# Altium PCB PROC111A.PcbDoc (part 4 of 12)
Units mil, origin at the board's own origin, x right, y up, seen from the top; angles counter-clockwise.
Board outline 7700 x 2300 mil, 6 copper layers (Top Layer, GND 1, SIG 1, SIG 2, GND 2, Bottom Layer), stack 61.062 mil thick; 841 components, 632 nets, 2914 pads, 1627 vias.
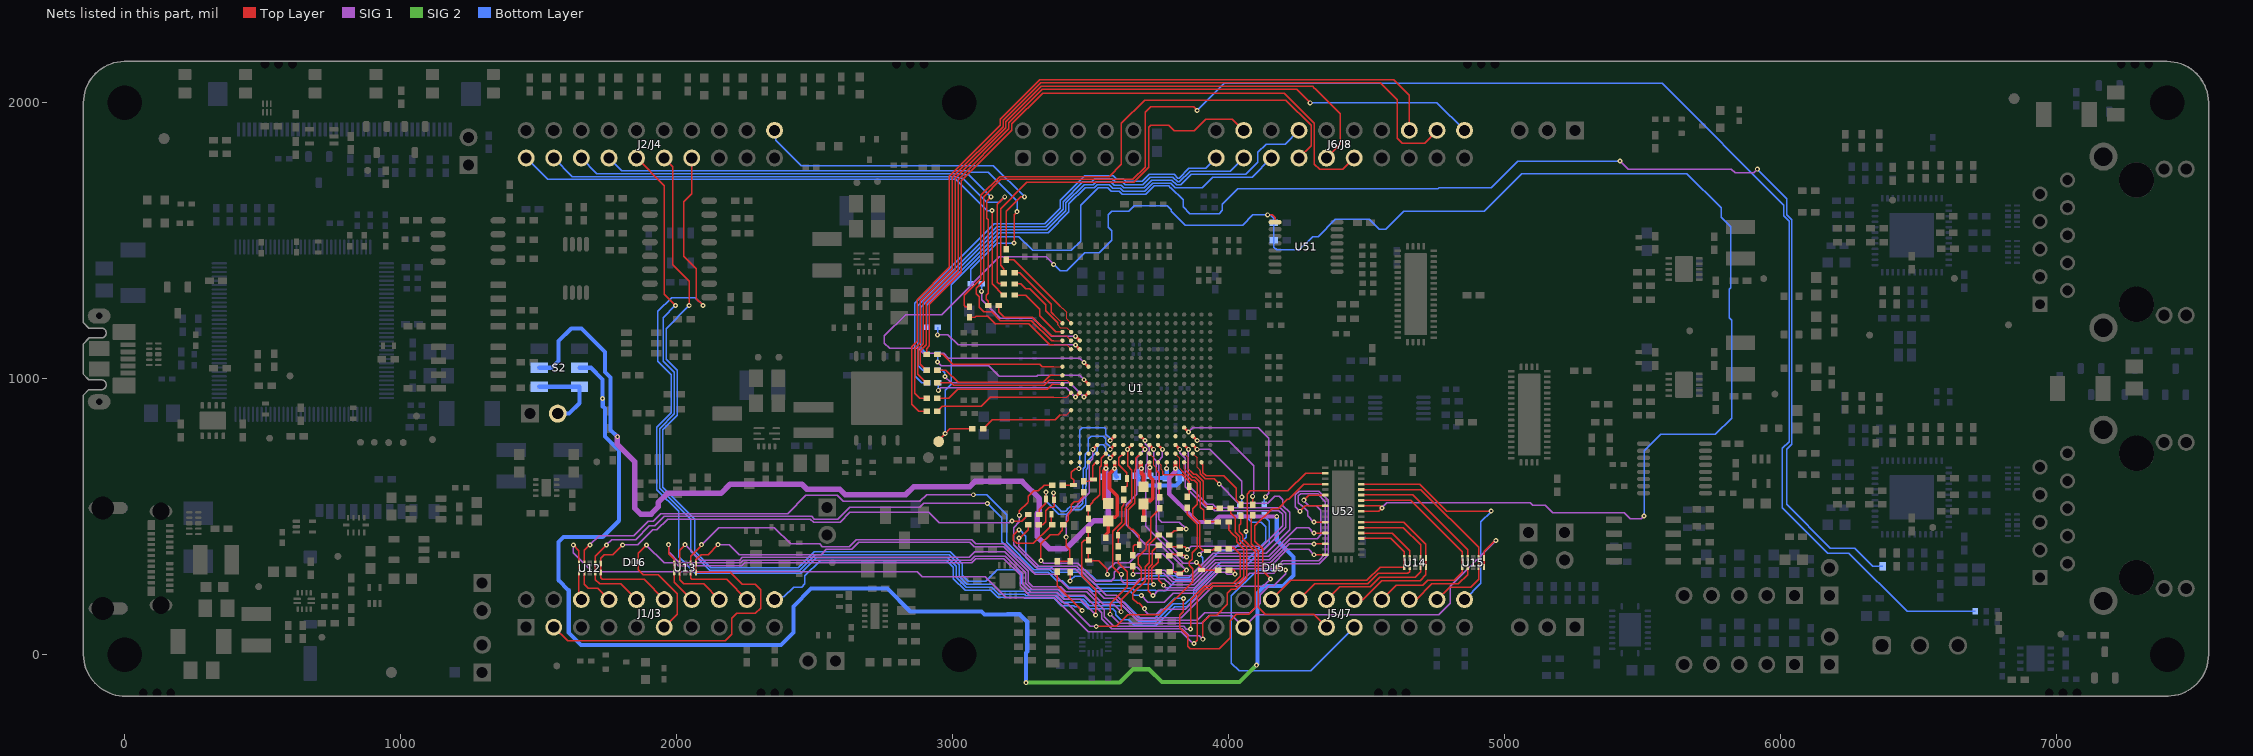
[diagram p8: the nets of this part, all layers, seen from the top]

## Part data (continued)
U38 U39 U40 U41: library part CMP-0073613-3, "4-Channel Ultra-Low-Capacitance IEC ESD Protection Diode, DQA0010A (USON-10)", Alternate Manufacturer="Texas Instruments"
U42: library part CMP-0079884-2, "Automotive High Speed CAN Transceiver, DRB0008J (VSON-8)", Alternate Manufacturer="Texas Instruments", Alternate PartNumber=TCAN1044VDRBRQ1
U43: library part CMP-0074359-2, "8-Bit Bidirectional Voltage-Level Shifter with Auto Direction Sensing and +/-15-kV ESD Protect, RGY0020A (VQFN-20)", Alternate Manufacturer="Texas Instruments"
U45: library part CMP-0036402-3, "Single Output High PSRR LDO, 1 A, Adjustable 1.2 to 5.5 V Output, 2.7 to 5.5 V Input, 8-pin SON (DRB), -40 to 125 degC, Green (RoHS & no Sb/Br)", Manufacturer="Texas Instruments"
U46: library part CMP-0051684-3, "Single Inverter, DCK0005A, LARGE T&R", F @ Nom Voltage(Max)(Mhz)=150, Generic Part Number=SN74LVC1G04, ICC @ Nom Voltage(Max)(mA)=0.01, Manufacturer="Texas Instruments", Operating Temperature Range(C)="-40 to 125,-40 to 85", Rating=Catalog, tpd @ Nom Voltage(Max)(ns)=7.5,5.2,4.2,3.7, Voltage(Nom)(V)=1.8,2.5,3.3,5
U48: library part CMP-0044782-1, "8-Bit LED Driver with I2C Interface, D0016A, TUBE", Generic Part Number=TPIC2810, Manufacturer="Texas Instruments", Operating Temperature Range(C)="-40 to 125", Rating=Catalog
U49 U51: library part CMP-0076540-1, "4-Bit One-of-2 FET Multiplexer/Demultiplexer 2.5-V/3.3-V Low-Voltage, High-Bandwidth Bus Switch, PW0016A (TSSOP-16)", Alternate Manufacturer="Texas Instruments"
U53: library part CMP-0090914-1, "Linear Voltage Regulator IC  1 Output  500mA SOT-23-5", Digikey Part Number=296-TLV75801PDBVTCT-ND, Dropout Voltage=720mV, Manufacturer="Texas Instruments", Max Supply Voltage=6V, Min Supply Voltage=1.5V, Mouser Part Number=595-TLV75801PDBVT, Nominal Supply Current=25uA, Operating Temperature Range="-40°C to +125°C", Output Voltage=0.55-5.5V
Y1: library part CMP-0084811-1, "Crystal, 25 MHz, 10 ppm, 4 pF, SMD", Frequency Stability="20 ppm", Frequency Tolerance="10 ppm", Frequency_Fixed=25MHz, Load Capacitance="4 pF", Manufacturer="Abracon Corporation", PartNumber=ABM10W-25.0000MHZ-8-K1Z-T3
Y2 Y4: library part CMP-0084811-1, "Crystal, 25 MHz, 10 ppm, 4 pF, SMD", Frequency_Fixed=25MHz, Frequency Stability="20 ppm", Frequency Tolerance="10 ppm", Load Capacitance="4 pF", Manufacturer="Abracon Corporation"
Y3: library part CMP-0004635-3, "Crystal, 16 MHz, 8pF, SMD", Frequency_Fixed=16MHz, Frequency Stability=+/-30ppm, Manufacturer=NDK, Supplier Part Number 1=644-1157-1-ND
ZZ1: library part CMP-0003616-3
ZZ2: library part CMP-0077236-1
ZZ3: library part CMP-0077237-1
ZZ4: library part CMP-0077238-1

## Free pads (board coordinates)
  round 65.36 on Mech16: 1(-431.58,264) 1(99.42,-97) 1(1046.42,125) 1(1053.42,-1023) 1(1354.42,103) 1(2235.42,-594)
  round 15.62 on Mech16: 1(3633.19,-429.05)

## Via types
v1: diameter 18, hole 8, Top Layer to Bottom Layer, tented both sides, 1523 vias
v2: diameter 19.68, hole 7.87, Top Layer to Bottom Layer, tented both sides, 104 vias

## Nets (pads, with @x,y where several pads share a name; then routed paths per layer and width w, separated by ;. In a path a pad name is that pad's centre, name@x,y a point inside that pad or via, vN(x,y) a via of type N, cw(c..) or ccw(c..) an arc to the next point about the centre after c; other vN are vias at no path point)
ADC_EXT_VREF: J17.2 S2.3 S2.6 | length 299.9
  Bottom Layer w15: S2.6@1501.87,971.1 S2.3@1647.54,971.1 1647.54,911.29 1610.02,873.77 J17.2@1568.62,873.77
AM263_ADC0_AIN0: J1/J3.23 R340.1 U12.1 U12.10 | length 3222.1
  Top Layer w5.3: v1(1625,398.33) 1645.54,377.79 1645.54,347.02 1645.63,346.93 U12.1@1645.63,298.04 1645.63,208.54 J1/J3.23@1654.17,200 ; v1(3874.15,41.16) 3885.32,52.33 3885.32,209.06 3914.83,238.57 3933.78,238.57 3942.74,247.52 4020.26,247.52 4054.6,281.86 4054.6,383.28 4028.31,409.58 4028.31,423.74 4013.06,438.98 4013.06,439.16 3999.53,452.69 R340.1@3999.53,485.1
  SIG 1 w4.75: v1(1625,398.33) 1625,370 1694.48,300.52 2871.61,300.52 2889.92,282.21 3118.36,282.21 3193.97,206.59 3368.18,206.59 3491.25,83.52 3826.88,83.52 3865.04,45.36 3866.37,45.36 3870.56,41.16 v1(3874.15,41.16)
AM263_ADC0_AIN0_R: C72.2 R340.2 U1.V15 | length 295.8
  Top Layer w4: U1.V15@3838.08,697.36 3838.08,674.99 3847.2,665.87
  Top Layer w5.3: 3847.2,665.87 3869.48,643.59 3877.89,643.59 3896.98,624.5 3896.98,535.28 3909.02,523.24 3909.02,519.81 3909.61,519.22 3909.61,490.61 3918.65,481.57 3959.69,481.57 R340.2@3960.16,481.1
AM263_ADC0_AIN1: J1/J3.28 R341.1 U13.2 U13.9 | length 2975.8
  Top Layer w5.3: v1(2030,398.85) 2010.31,379.17 U13.9@2010.31,331.44 U13.2@2010.31,298.56 2010.31,271.62 2025,256.94 2097.24,256.94 J1/J3.28@2154.17,200 ; v1(3905.77,56.49) 3905.77,117.61 3932.29,144.13 3956.34,144.13 3995.21,183 3995.21,223.7 4008.43,236.92 4024.65,236.92 4065.2,277.47 4065.2,389.68 4039.16,415.72 4039.16,427.88 4023.66,443.37 4023.66,496.83 4014.1,506.39 4013.73,506.39 4006.44,513.68 R341.1@4006.44,531.48
  SIG 1 w4.75: v1(2030,398.85) 2085.58,343.27 2227.62,343.27 2237.5,353.15 2360.03,353.15 2360.19,353 3060.27,353 3080.22,372.95 3188.76,372.95 3263.9,297.81 3263.9,258.91 3286.07,236.74 3383.95,236.74 3405.82,214.87 3476.39,214.87 3538.87,152.39 3538.87,130.9 3576.14,93.62 3832.09,93.62 3856.21,69.51 3892.76,69.51 v1(3905.77,56.49)
AM263_ADC0_AIN1_R: C73.2 R341.2 U1.U15 | length 279.7
  Top Layer w4: U1.U15@3838.08,728.86 3853.83,713.11 3853.83,687.18 3853.57,686.92 3853.57,674.49 3862.19,665.87
  Top Layer w5.3: 3862.19,665.87 3873.87,654.19 3882.28,654.19 3907.74,628.73 3907.74,550.3 3921.72,536.33 3926.57,531.48 R341.2@3967.07,531.48
AM263_ADC0_AIN2: R342.1 U52.32 | length 1359.4
  Top Layer w5.3: v1(3725,214.8) 3708.32,231.48 3708.32,262.41 3709.39,263.48 3709.39,316.29 3722.09,328.98 3722.09,376.01 3738.24,392.17 3740.33,392.17 R342.1@3747.53,399.36 ; v1(4308.39,480.63) U52.32@4350.04,480.63
  SIG 1 w4.75: v1(3725,214.8) 3726.31,214.8 3745.29,233.78 3757.68,233.78 ccw(c3763.78,252.04) 3769.89,233.78 3881.81,233.78 3957.71,309.68 3958.63,309.68 3960.34,311.39 4164.51,311.39 4194.74,341.63 4325.29,341.63 4350,366.34 4350,555.26 4321.93,583.33 4259.82,583.33 4252.51,576.02 4252.51,550.44 4263.71,539.25 4265.75,539.25 4285.8,519.2 4285.8,503.22 v1(4308.39,480.63)
AM263_ADC0_AIN2_LIN1_TXD: J5/J7.66 U14.5 U14.6 U52.7 | length 675.5
  Top Layer w5.3: J5/J7.66@4454.17,200 4485.87,200 4554.19,268.33 4692.8,268.33 4714.37,289.89 U14.5@4714.37,317.68 U14.6@4714.37,350.55 4714.37,400.24 4633.98,480.63 U52.7@4479.96,480.63
AM263_ADC0_AIN2_R: C74.2 R342.2 U1.T14 | length 1052.8
  Top Layer w5.3: R342.2@3784.9,396.86 3790.09,391.67 C74.2@3822.14,391.67 ; C74.2@3822.33,391.86 3839.55,391.86 v1(3850.16,381.25)
  Top Layer w10: U1.T14@3806.58,760.35 v1(3822.33,744.61)
  SIG 1 w4.75: v1(3822.33,744.61) 3823.05,743.89 3823.05,732.02 3842.32,712.74 3842.32,609.75 3916.91,535.16 3936.17,535.16 3949.33,522 4181.53,522 4195.09,508.45 4195.09,468.37 4120.85,394.14 3863.06,394.14 v1(3850.16,381.25)
AM263_ADC0_AIN3: J1/J3.2 R343.1 U13.5 U13.6 | length 3696.3
  Top Layer w5.3: J1/J3.2@1554.17,100 1604.17,50 2175,50 2200,75 2200,132.66 2217.34,150 2284.55,150 2303.98,169.43 2303.98,236.33 2284.2,256.12 2236.48,256.12 2194.04,298.56 U13.5@2069.37,298.56 U13.6@2069.37,331.44 2069.37,344.53 2088.22,363.38 2113.53,363.38 v1(2149,398.85) ; v1(3861.25,93.33) 3861.25,199.99 3910.44,249.17 3929.39,249.17 3939.44,259.22 4016.97,259.22 4041.81,284.06 4041.81,364.91 4018.4,388.31 R343.1@4000.24,388.31
  SIG 1 w4.75: v1(2149,398.85) 2190.51,398.85 2224.76,364.6 2226.16,363.2 2473.83,363.2 ccw(c2476.27,382.3) 2478.71,363.2 2523.19,363.2 2541.67,381.69 2634.16,381.69 2660,407.53 3061.43,407.53 3077.22,391.74 3184.19,391.74 3273.95,301.97 3273.95,263.08 3290.24,246.79 3341.46,246.79 3341.54,246.87 3390.95,246.87 3409.9,227.92 3484.58,227.92 3549.39,163.11 3549.39,138.09 3583.81,103.67 3836.26,103.67 3846.6,93.33 v1(3861.25,93.33)
AM263_ADC0_AIN3_R: C75.2 R343.2 U1.U14 | length 469.4
  Top Layer w4: U1.U14@3806.58,728.86 3822.4,713.04 3822.4,675.67 3832.21,665.87
  Top Layer w5.3: 3832.21,665.87 3865.09,632.99 3865.74,632.34 3874.15,632.34 3882.22,624.27 3885.32,621.17 3885.32,545.42 3869.57,529.67 3869.57,503.87 3895.5,477.94 3895.5,388.99 3905.77,378.72 3919.53,378.72 C75.2@3922.62,375.63 3926.56,379.57 3942.57,379.57 3947.81,384.81 R343.2@3960.87,384.81
AM263_ADC0_AIN4: U1.U13
AM263_ADC0_AIN5: U1.R14
AM263_ADC1_AIN0: J1/J3.24 R344.1 U12.2 U12.9 | length 2712.9
  Top Layer w5.3: v1(1685,398.33) 1665.31,378.64 U12.9@1665.31,330.91 U12.2@1665.31,298.04 1665.31,255.72 1680,241.04 1713.14,241.04 J1/J3.24@1754.17,200 ; v1(3727.84,254.71) 3727.84,258.14 3723.29,262.7 3723.29,263.52 3721.11,265.69 3721.11,313.02 3744,335.9 R344.1@3744,363.46
  SIG 1 w4.75: v1(1685,398.33) 1718.5,431.83 1844.64,431.83 1897.24,484.43 1914.46,484.43 1941.94,511.91 2401.38,511.91 2466.67,577.19 2581.8,577.19 2603.25,555.75 2880.87,555.75 2905,579.88 v1(3074.39,579.88)
  Bottom Layer w5.3: v1(3074.39,579.88) 3122.73,579.88 3195.17,507.44 3195.17,407.23 3293.57,308.84 3350.78,308.84 3361.17,298.44 3470.53,298.44 3514.26,254.71 v1(3727.84,254.71)
AM263_ADC1_AIN0_R: C81.2 R344.2 U1.T11 | length 543.3
  Top Layer w4.75: R344.2@3783.59,358.71 3789.38,364.5 C81.2@3822.09,364.5 3826.37,360.23 3837.89,360.23 3843.99,354.12 v1(3847.29,354.12)
  Top Layer w10: U1.T11@3712.09,760.35 v1(3727.84,744.61)
  SIG 1 w4.75: v1(3727.84,744.61) 3727.84,711.98 3736.34,703.48 3736.34,449.7 3833.95,352.09 3845.26,352.09 v1(3847.29,354.12)
AM263_ADC1_AIN1: J1/J3.29 R345.1 U13.4 U13.7 | length 2509.8
  Top Layer w5.3: v1(2090,398.85) 2090,397.53 2049.68,357.21 U13.7@2049.68,331.44 U13.4@2049.68,298.56 2049.68,278.15 2055,272.84 2181.34,272.84 J1/J3.29@2254.17,200 ; v1(3610.1,156.01) 3610.1,199.87 3683.1,272.88 3683.1,316.09 3671.69,327.49 3671.69,355.57 3700.52,384.4 3700.52,404.84 3716.89,421.21 3716.89,437.64 3716.84,437.69 3716.84,496.81 3749.25,529.22 R345.1@3749.25,531.19
  SIG 1 w4.75: v1(2090,398.85) 2151.71,460.56 2353.7,460.56 2412.27,401.98 2517.05,401.98 2527.3,391.74 2624.16,391.74 2650,417.58 3067.79,417.58 3072.78,412.58 ccw(c3087.35,425.17) 3074.76,410.6 3081.99,403.38 3083.38,401.98 3188.15,401.98 3298.87,291.27 3368.35,291.27 3420.44,239.17 3489.77,239.17 3545.45,183.5 3582.61,183.5 v1(3610.1,156.01)
AM263_ADC1_AIN1_R: C82.2 R345.2 U1.U11 | length 173.7
  Top Layer w4: U1.U11@3712.09,728.86 3727.84,713.11 3727.84,687.51 3739.34,676 3739.34,666.6
  Top Layer w5.3: 3739.34,666.6 3748.34,657.61 C82.2@3748.34,611.49 3748.34,571.47 R345.2@3749.25,570.56
AM263_ADC1_AIN2: R346.1 U52.29 | length 1594.8
  Top Layer w5.3: v1(3694.53,167.18) 3674.93,186.78 3669.77,186.78 3652.61,203.94 3652.61,222.39 3697.55,267.34 3697.55,319.44 3711.16,333.05 3711.16,399.68 R346.1@3745.56,434.08 ; v1(4257.78,520) 4277.46,539.69 U52.29@4350.04,539.68
  SIG 1 w4.75: v1(3694.53,167.18) 3697.07,164.65 3697.07,158.16 3708.27,146.95 3736.44,146.95 3754.47,164.99 3841.74,164.99 3935.97,259.22 4038.86,259.22 4075.37,295.74 4163.07,295.74 4197.33,330 4327.87,330 4360.05,362.18 4360.05,559.42 4326.09,593.38 4255.66,593.38 4241.44,579.16 4241.44,536.34 v1(4257.78,520)
AM263_ADC1_AIN2_R: C83.2 R346.2 U1.T12 | length 464.4
  Top Layer w5.3: R346.2@3784.9,434.08 3786.87,434.08 3802.2,449.41 3811.22,449.41 3817.83,456.02 C83.2@3822.33,456.02 v1(3845.71,456.02)
  Top Layer w10: U1.T12@3743.59,760.35 v1(3759.34,744.61)
  SIG 1 w4.75: v1(3759.34,744.61) 3759.34,716.89 3746.39,703.94 3746.39,491.85 3757.61,480.63 3821.1,480.63 v1(3845.71,456.02)
AM263_ADC1_AIN2_SDFM0_D2: J5/J7.67 U15.1 U15.10 U52.11 | length 849.4
  Top Layer w5.3: U52.11@4479.96,559.37 4659.22,559.37 4846.03,372.56 U15.10@4846.03,350.69 U15.1@4846.03,317.82 4846.03,299.84 4816.96,270.77 4721.28,270.77 4702.93,252.43 4606.6,252.43 J5/J7.67@4554.17,200
AM263_ADC1_AIN3: D16.1 J1/J3.6 R347.1 | length 2928.9
  Top Layer w5.3: v1(1890,397.76) 1860.51,368.27 D16.1@1860.51,335.1 1860.51,307.6 1878.08,290.03 1932.25,290.03 2001,221.28 2001,146.83 J1/J3.6@1954.17,100 ; v1(3519.72,102.77) 3591.39,102.77 3633.62,145 3748.39,145 3868.57,265.17 3868.57,312.28 3857.03,323.82 3857.03,336.25 3865.26,344.48 3865.26,345.08 3866.82,346.65 3866.82,370.13 3884.9,388.22 3884.9,473.55 3849.44,509.01 R347.1@3849.44,532.41
  SIG 1 w4.75: v1(1890,397.76) 1954.54,333.22 1995.09,333.22 2005.14,323.17 2235.95,323.17 2245.83,333.05 2351.71,333.05 2351.86,332.9 3068.59,332.9 3083.48,347.79 3185.5,347.79 3243.8,289.49 3243.8,250.59 3277.75,216.64 3374.86,216.64 3406,185.51 3415.94,185.51 3498.68,102.77 v1(3519.72,102.77)
AM263_ADC1_AIN3_R: C84.2 R347.2 U1.V12 | length 218.2
  Top Layer w4: U1.V12@3743.59,697.36 3755,685.95 3755,672.02 3761.16,665.87
  Top Layer w5.3: 3761.16,665.87 3761.16,654.74 3764.26,651.63 3831.45,651.63 3854.49,628.6 3856.86,626.23 3856.86,610.08 C84.2@3856.76,609.98 3856.76,581.07 3849.44,573.75 R347.2@3849.44,571.78 R347.2@3851.76,574.1
AM263_ADC1_AIN4: U1.U12
AM263_ADC1_AIN5: U1.R12
AM263_ADC2_AIN0: J1/J3.25 R348.1 U12.4 U12.7 | length 2951.3
  Top Layer w5.3: v1(1745,398.33) 1745,397.18 1704.68,356.86 U12.7@1704.68,330.91 U12.4@1704.68,298.04 1704.68,272.25 1720,256.94 1797.24,256.94 J1/J3.25@1854.17,200 ; R348.1@4001.95,307.98 4019.18,307.98 4022.28,304.87 v1(4022.28,292.14)
  SIG 1 w4.75: v1(1745,398.33) 1764.25,417.58 1851,417.58 1900.37,466.95 1920.03,466.95 1954.94,501.86 2488.47,501.86 2498.59,491.74 2583.26,491.74 2626.52,535 2881.05,535 2894.71,548.66 v1(3125,548.66) ; v1(3683.06,215.21) 3707.24,191.03 3766.9,191.03 3799.6,223.73 3885.97,223.73 3961.87,299.63 3986.82,299.63 3994.31,292.14 v1(4022.28,292.14)
  Bottom Layer w5.3: v1(3125,548.66) 3177.41,496.25 3177.41,409.94 3180.52,406.83 3180.58,406.83 3289.18,298.24 3346.39,298.24 3376.21,268.41 3396.55,268.41 3419.86,245.1 3491.11,245.1 3492,244.21 3492.65,244.21 3507.18,229.69 3643.7,229.69 3658.18,215.21 v1(3683.06,215.21)
AM263_ADC2_AIN0_R: C85.2 R348.2 U1.R10 | length 684.7
  Top Layer w5.3: v1(3882.78,335) 3901.07,316.7 C85.2@3901.07,306.72 3961.26,306.72 R348.2@3961.35,306.81 ; R348.2@3957.78,305.21 R348.2@3961.35,305.21
  Top Layer w10: U1.R10@3680.6,791.85 v1(3696.35,776.1)
  SIG 1 w4.75: v1(3696.35,776.1) 3698.12,774.33 3698.12,764.57 3707.22,755.48 3711.72,750.97 3711.72,738.24 3705.24,731.76 3705.24,693.11 3698.38,686.25 3698.38,671.18 3699.68,669.88 3699.68,466.6 3835.08,331.19 3873.37,331.19 3874.64,332.46 3880.24,332.46 v1(3882.78,335)
AM263_ADC2_AIN1: R349.1 U52.38 | length 711.5
  Top Layer w5.3: R349.1@3746.22,301.47 3746.22,269.6 v1(3763.78,252.04) ; v1(4308.39,362.52) U52.38@4350.04,362.52
  SIG 1 w4.75: v1(3763.78,252.04) 3770.6,245.22 3771.99,243.83 3876.73,243.83 3956.26,323.37 4153.93,323.37 4212.33,381.77 4289.14,381.77 v1(4308.39,362.52)
AM263_ADC2_AIN1_MCAN1_RX: J5/J7.63 U14.1 U14.10 U52.4 | length 761.7
  Top Layer w5.3: J5/J7.63@4154.17,200 4224.17,270 4500.72,270 4548.4,317.68 U14.1@4635.63,317.68 U14.10@4635.63,350.55 4635.63,373.58 4587.64,421.57 U52.4@4479.96,421.57
AM263_ADC2_AIN1_R: C86.2 R349.2 U1.T10 | length 680.3
  Top Layer w5.3: R349.2@3785.59,301.47 3810.25,301.47 3817.59,294.13 C86.2@3822.09,294.13 3826.94,298.98 3831.44,298.98 3836.48,304.03 3844.35,304.03 v1(3846.78,306.46)
  Top Layer w10: U1.T10@3680.6,760.35 v1(3696.35,744.61)
  SIG 1 w4.75: v1(3696.35,744.61) 3666.51,714.77 3666.51,582.19 3627.92,543.61 3627.92,471.52 3699.86,399.58 3752.48,399.58 3845.61,306.46 v1(3846.78,306.46)
AM263_ADC2_AIN2: R350.1 U52.27 | length 1042.7
  Top Layer w5.3: R350.1@3652.3,322.09 3652.9,321.48 v1@3652.9,295.01 ; v1(4271.79,560.22) 4290.46,578.89 4340.88,578.89 U52.27@4350.04,579.06
  SIG 1 w4.75: v1@3652.9,295.01 3653.14,295.25 3764.5,295.25 3794.07,265.67 3795.46,264.28 3868.75,264.28 3949.12,344.65 4146.79,344.65 4223.28,421.14 4319.66,421.14 4332.6,434.08 4332.6,523.74 4316.22,540.12 4290.36,540.12 4271.79,558.7 v1(4271.79,560.22)
  other v1: 3652.9,291.63
AM263_ADC2_AIN2_R: C87.2 R350.2 U1.U10 | length 425.8
  Top Layer w5.3: R350.2@3651.61,360.75 3653.9,363.04 3653.9,392.72 3660.09,398.92 C87.2@3675.6,398.92 3675.6,430.76 3651.97,454.39 cw(c3657.41,473.14) 3651.42,454.55 3645.88,454.55 3635.6,464.83 3635.6,525.15 3659.7,549.26 3659.7,669.49 3663.63,673.41 3663.63,711.89 U1.U10@3680.6,728.86
AM263_ADC2_AIN2_SDFM0_CLK2: J5/J7.68 U15.2 U15.9 U52.12 | length 806.7
  Top Layer w5.3: U52.12@4479.96,579.06 4666.89,579.06 4865.48,380.47 4865.48,350.94 U15.9@4865.72,350.69 U15.2@4865.72,317.82 4865.72,290.75 4831.63,256.67 4736.04,256.67 4679.37,200 J5/J7.68@4654.17,200
AM263_ADC2_AIN3: J5/J7.42 R351.1 U15.5 U15.6 | length 1973.5
  Top Layer w4.75: v1(3570.36,146.95) 3570.36,184.55 3632.4,246.59 3632.4,301.06 3606.72,326.75 3600.03,333.43 R351.1@3600.03,360.84
  Top Layer w5.3: U15.5@4924.77,317.82 U15.6@4924.77,350.69 4924.77,374.58 4964.27,414.07 v1(4967.27,414.07)
  SIG 1 w5.3: v1(3570.36,146.95) 3603.11,114.2 3902.67,114.2 3929.76,141.3 4012.88,141.3 J5/J7.42@4054.17,100 4099.91,145.74 4760.36,145.74 4802,187.38 4802,248.8 v1(4967.27,414.07)
AM263_ADC2_AIN3_R: C88.2 R351.2 U1.T9 | length 401.8
  Top Layer w5.3: R351.2@3599.24,393.49 3598.81,393.93 C88.2@3598.81,432.5 3597.75,433.57 3597.75,449.35 3625,476.6 3625,529.54 3649.1,553.65 3649.1,668.6 3633.35,684.34 v1(3633.35,744.61)
  Top Layer w10: v1(3633.35,744.61) U1.T9@3649.1,760.35
AM263_ADC2_AIN4_R: U1.V9
AM263_ADC2_AIN5_R: U1.T8
AM263_ADC3_AIN0: J1/J3.26 R352.1 U12.5 U12.6 | length 1989.9
  Top Layer w5.3: v1(1804,398.33) 1768.53,362.86 1737.02,362.86 1724.37,350.2 U12.6@1724.37,330.91 U12.5@1724.37,298.04 1724.37,278.47 1730,272.84 1881.34,272.84 J1/J3.26@1954.17,200 ; v1(3214.69,484.76) 3249.75,484.76 3264.07,499.08 3264.07,501.05 3271.26,508.24 R352.1@3273.23,508.24
  SIG 1 w4.75: v1(1804,398.33) 1857.95,398.33 1912.12,452.5 1928.03,452.5 1967.34,491.81 2484.3,491.81 2496.13,479.98 2591.65,479.98 2627.44,515.76 2913.65,515.76 2950.51,478.9 3205.29,478.9 3211.14,484.76 v1(3214.69,484.76)
AM263_ADC3_AIN0_R: C92.2 R352.2 U1.U7 | length 632.1
  Top Layer w5.3: R352.2@3312.6,508.24 3312.6,524.82 3337.3,549.52 C92.2@3337.3,564.5 3337.58,564.78 3337.58,588.9 v1(3337.87,589.18)
  Top Layer w10: v1(3570.36,713.11) U1.U7@3586.11,728.86
  Bottom Layer w5.3: v1(3337.87,589.18) 3337.87,555.77 3384.12,509.51 3413.3,509.51 3429.08,525.3 3463.04,525.3 3481.33,543.59 3481.33,611.27 3482.93,612.87 3482.93,670.88 3489.4,677.35 3489.4,703.42 3522.99,737.02 3522.99,738.09 3523.22,738.32 3523.22,751.09 3532.38,760.26 3545.35,760.26 3554.61,750.99 3554.61,732.44 3570.36,716.7 v1(3570.36,713.11)
AM263_ADC3_AIN1: R353.1 U52.36 | length 1143.9
  Top Layer w5.3: v1@3610.51,288.72 3579.35,319.88 3579.35,447.76 3611.72,480.13 3611.72,535.38 3620.06,543.72 R353.1@3620.06,560.98 ; v1(4308.39,401.89) U52.36@4350.04,401.89
  SIG 1 w4.75: v1(3610.51,291.63) 3610.51,269.49 3618.98,261.02 3663.01,261.02 3678.02,276.04 3767,276.04 3787.77,255.27 3789.16,253.88 3872.56,253.88 3952.6,333.92 4150.27,333.92 4218.24,401.89 v1(4308.39,401.89)
AM263_ADC3_AIN1_MCAN1_TX: J5/J7.64 U14.2 U14.9 U52.5 | length 721
  Top Layer w5.3: J5/J7.64@4254.17,200 4312.03,257.86 4503.57,257.86 4540.71,295 4649.14,295 4655.31,301.17 U14.2@4655.31,317.68 U14.9@4655.31,350.55 4655.31,377.33 4591.39,441.26 U52.5@4479.96,441.26
AM263_ADC3_AIN1_R: C93.2 R353.2 U1.U8 | length 153.2
  Top Layer w5.3: U1.U8@3617.61,728.86 3601.86,713.11 3601.86,689.21 3630.94,660.13 C93.2@3630.94,638.55 3631.83,637.66 3631.83,612.61 3628.72,609.51 3627.25,609.51 3620.06,602.32 R353.2@3620.06,600.35
AM263_ADC3_AIN2: R354.1 U52.25 | length 1704.4
  Top Layer w5.3: v1(3239.44,422.84) 3242.23,422.84 3272.8,453.41 R354.1@3272.8,471.26 ; v1(4151.58,274.88) 4122.16,304.3 4122.16,383.74 4094.47,411.44 4094.47,467.42 4156.93,529.89 4178.83,529.89 4212.33,563.38 4217,563.38 4272.04,618.43 U52.25@4350.04,618.43
  SIG 1 w4.75: v1(3239.44,422.84) 3239.44,393.71 3305.06,328.09 ccw(c3319.37,340.98) 3306.48,326.67 3311.43,321.73 3449.05,321.73 3555.56,215.21 3592.41,215.21 3672.5,135.12 3828.25,135.12 3940.99,247.87 4124.56,247.87 v1(4151.58,274.88)
AM263_ADC3_AIN2_R: C94.2 R354.2 U1.T7 | length 702.9
  Top Layer w5.3: R354.2@3312.17,471.26 3312.77,471.86 3325.79,471.86 3336.57,482.64 3336.57,522.5 3349.23,535.17 3363.52,535.17 3366.75,538.39 C94.2@3366.75,562.35 3365.78,563.31 3365.78,586.07 v1(3364.82,587.04)
  Top Layer w10: v1(3570.36,744.61) U1.T7@3586.11,760.35
  Bottom Layer w5.3: v1(3364.82,587.04) 3364.82,548.82 3393.53,520.11 3408.73,520.11 3413.81,525.19 ccw(c3401.66,540.48) 3416.95,528.33 3425.02,536.4 3458.47,536.4 3470.49,548.42 3470.49,615.42 3472.33,617.26 3472.33,673.87 3479.87,681.42 3479.87,726.47 3491.52,738.12 3491.52,782.39 3500.89,791.75 3545.35,791.75 3554.52,782.58 3554.52,769.15 3568.06,755.61 3568.06,746.91 v1(3570.36,744.61)
AM263_ADC3_AIN2_SDFM0_D3: J5/J7.69 U15.4 U15.7 U52.13 | length 809
  Top Layer w5.3: U52.13@4479.96,598.74 4695.44,598.74 4905.09,389.09 U15.7@4905.09,350.69 U15.4@4905.09,317.82 4905.09,273.4 4877.2,245.51 4799.68,245.51 J5/J7.69@4754.17,200
AM263_ADC3_AIN3: D15.1 J5/J7.46 R355.1 | length 2532.9
  Top Layer w5.3: v1(3240.9,505.3) 3240.9,521.19 3270.73,551.01 3270.73,551.76 3273.91,554.94 3273.91,575.27 3292.48,593.85 3310.12,593.85 3330.76,614.48 R355.1@3359.5,614.48 ; D15.1@4176.3,315.32 4195.89,315.32 4204.49,306.72 v1(4205.69,306.72)
  SIG 1 w4.75: v1(3240.9,505.3) 3240.9,481.27 3220.19,460.56 3220.19,398.37 3289.23,329.34 3307.2,311.37 3443.22,311.37 3549.43,205.16 3588.25,205.16 3668.55,124.86 3885.75,124.86 3912.88,151.99 4078.02,151.99 4113.41,187.38 4113.41,216.88 4146.53,250 4162.64,250 4182.9,270.26 4205.69,293.06 v1(4205.69,306.72)
  Bottom Layer w5.3: v1(4205.69,306.72) 4102.86,306.72 4009.63,213.49 4009.63,-29.78 4037.74,-57.89 4296.28,-57.89 J5/J7.46@4454.17,100
AM263_ADC3_AIN3_R: C95.2 R355.2 U1.R7 | length 431.1
  Top Layer w5.3: R355.2@3398.87,614.48 3398.97,614.59 C95.2@3435.03,614.59 ; C95.2@3437.53,614.59 3437.53,633.42 3429.85,641.1 3429.85,661.3 3443.15,674.6 3456.52,674.6 v1(3456.68,674.44)
  Top Layer w10: v1(3570.36,776.1) U1.R7@3586.11,791.85
  Bottom Layer w5.3: v1(3456.68,674.44) 3459.11,676.87 3459.11,682.97 3460.03,683.89 3460.03,776 3460.03,813.88 3469.59,823.44 3549.7,823.44 3554.71,818.44 3554.71,798.9 3567.83,785.78 3567.83,778.64 v1(3570.36,776.1)
AM263_ADC3_AIN4: U1.V8
AM263_ADC3_AIN5: U1.U9
AM263_ADC4_AIN0: J1/J3.27 R356.1 R358.1 U13.1 U13.10 | length 2293.4
  Top Layer w5.3: v1(1970,398.85) 1970,365.99 1990.63,345.36 U13.10@1990.63,331.44 U13.1@1990.63,298.56 1990.63,263.54 J1/J3.27@2054.17,200 ; R356.1@3491.62,452.87 R358.1@3491.62,415.72 3476.57,415.72 3467.37,406.52 3467.37,286.12 3517.58,235.91 v1(3517.58,144.55)
  SIG 1 w4.75: v1(1970,398.85) 1970,372.52 2009.3,333.22 2231.78,333.22 2241.67,343.1 2355.87,343.1 2356.03,342.95 3064.43,342.95 3079.32,357.84 3189.66,357.84 3253.85,293.65 3253.85,254.75 3281.91,226.69 3379.03,226.69 3405.25,200.47 3461.66,200.47 v1(3517.58,144.55)
AM263_ADC4_AIN0_R: C96.2 R356.2 U1.U6 | length 263.4
  Top Layer w5.3: R356.2@3491.62,492.24 3490.84,493.02 3490.84,535.32 3507.37,551.84 3507.37,556.13 3531.85,580.61 3531.85,679.85 3537.64,685.64 3537.64,711.89 U1.U6@3554.61,728.86
AM263_ADC4_AIN1: R357.1 R359.1 U52.34 | length 1533.9
  Top Layer w5.3: v1(3319.37,340.98) 3319.37,402.29 3352.45,435.38 3381.19,435.38 3396.93,451.11 3396.93,468.53 R359.1@3399.65,471.26 3401.62,471.26 3408.81,478.45 3408.81,478.69 3417.64,487.52 3417.64,509.98 3428.71,521.05 3428.71,543.35 3440.73,555.37 3453.67,555.37 3470.42,572.12 3470.42,584.92 R357.1@3474.28,588.78 ; v1(4308.39,441.26) U52.34@4350.04,441.26
  SIG 1 w4.75: v1(3319.37,340.98) 3319.57,340.98 3328.77,331.78 3453.21,331.78 3517.79,267.2 3573.44,267.2 3585.74,279.5 3585.74,298.84 3604.55,317.66 3667.57,317.66 3678.51,306.72 3768.29,306.72 3800.46,274.55 3864.81,274.55 3948.1,357.84 4144.17,357.84 4246.84,460.51 4289.14,460.51 v1(4308.39,441.26)
AM263_ADC4_AIN1_LIN1_RXD: J5/J7.65 U14.4 U14.7 U52.6 | length 721.4
  Top Layer w5.3: J5/J7.65@4354.17,200 4401.43,247.26 4512,247.26 4546.12,281.38 4676.04,281.38 4694.69,300.03 U14.4@4694.69,317.68 U14.7@4694.69,350.55 4694.69,399.17 4632.91,460.94 U52.6@4479.96,460.94
AM263_ADC4_AIN1_R: C97.2 R357.2 U1.V5 | length 106.9
  Top Layer w5.3: R357.2@3474.28,628.15 3491.13,628.15 3493.9,630.93 3505.56,630.93 C97.2@3509.8,635.17 3506.39,638.58 3506.39,685.64 U1.V5@3518.12,697.36
AM263_ADC4_AIN2: U1.V4
AM263_ADC4_AIN3: U1.U5
AM263_ADC4_AIN4: U1.V3
AM263_ADC4_AIN5: U1.U4
AM263_ADC_CAL0_R: C251.2 R358.2 U1.U16 | length 1516.2
  Top Layer w4: U1.U16@3869.57,728.86 3885.32,713.11 3885.32,679.84 3895.5,669.66 3895.5,666.6
  Top Layer w5.3: C251.2@3491.36,341.22 3491.62,341.48 R358.2@3491.62,376.35 ; C251.2@3491.62,341.22 3529.46,341.22 3560.18,310.5 v1(3560.18,291.63) ; 3895.5,666.6 3895.72,666.39 3895.72,655.74 3914.22,637.24 3947.25,637.24 v1(3965.39,619.1)
  SIG 1 w5.3: v1(3560.18,291.63) 3560.18,305.98 3588.1,333.9 3639.71,333.9 3672.15,366.34 3759.87,366.34 3797.92,328.3 3797.92,302.72 3815.06,285.58 3861.23,285.58 3943.91,368.25 4136.39,368.25 4220.54,452.4 4220.54,515.83 4195.98,540.4 4195.98,561.87 4183.13,574.71 4165.94,574.71 4140.8,549.58 4034.91,549.58 v1(3965.39,619.1)
AM263_ADC_CAL1_R: C252.2 R359.2 U1.T15 | length 2071.1
  Top Layer w5.3: v1(3239.66,452.8) 3219.92,433.07 3219.92,414.75 3231.36,403.32 3292.34,403.32 3351.12,462.1 3351.12,464.06 3358.31,471.26 R359.2@3360.28,471.26 3357.4,474.13 C252.2@3357.4,508.89 ; v1@3893.18,362.86 v1(3893.18,363.71)
  Top Layer w10: U1.T15@3838.08,760.35 v1(3853.83,744.61)
  SIG 1 w4.75: v1(3853.83,744.61) 3853.98,744.45 3853.98,687.86 3853.19,687.07 3853.19,614.25 3921.57,545.88 3941.42,545.88 3954.62,532.68 4186.8,532.68 4207.07,512.41 4207.07,461.93 4125.85,380.71 3910.18,380.71 v1(3893.18,363.71)
  Bottom Layer w5.3: v1(3239.66,452.8) 3242.19,452.8 3265.03,429.97 3265.03,352.95 3298.54,319.44 3355.17,319.44 3365.56,309.05 3479.15,309.05 3518.88,269.32 3686.77,269.32 3702.98,285.54 3808.69,285.54 3815.81,278.41 3854.32,278.41 3905,329.09 3905,351.89 v1(3893.18,363.71)
AM263_ADC_VREFHI_G01: C77.1 C79.1 C80.1 S2.2 U1.V10 U1.V14 | length 5807.8
  Top Layer w15: U1.V10@3680.6,697.36 3680.74,697.22 3680.74,678.57 3683.01,676.31 v1(3683.01,675.5) 3683.58,674.92 3683.58,657.97 3691,650.55 C77.1@3691,608.87 ; v1(3806.58,675) U1.V14@3806.58,697.36
  SIG 1 w15: v1(3806.58,675) 3806.01,674.43 3806.01,663.29 3784.21,641.49 3784.21,582.96 3805.95,561.23 3842.86,524.32 3886.54,480.63 3944.65,480.63 3965.3,501.28 v1(4173.75,501.28)
  SIG 2 w15: v1(3265.1,-100.99) 3604.81,-100.99 3653.53,-52.28 3710.62,-52.28 3757.51,-99.16 4038.47,-99.16 v1(4100.04,-37.59)
  Bottom Layer w15: S2.2@1647.54,1040 1689.19,1040 1731.26,997.93 v1(1731.26,929.09) 1731.83,928.52 1731.83,900.23 1739.7,892.36 1739.7,791.31 1790.19,740.81 1790.19,485.58 1731.78,427.17 1590,427.17 1571.61,408.78 1571.61,270.34 1608.29,233.67 1608.29,80.99 1653.23,36.05 2377.4,36.05 2422.27,80.92 2422.27,175.63 2486.45,239.82 2763.41,239.82 2845.96,157.27 3104.23,157.27 3115.01,146.48 3197.61,146.48 3197.8,146.67 3242.64,146.67 3269.8,119.51 3269.8,12.01 3265.1,7.31 v1(3265.1,-100.99) ; C79.1@3665.62,649.09 3667.61,649.09 3671.92,653.4 3671.92,663.6 3683.01,674.68 v1(3683.01,675.5) ; C79.1@3673.14,639.94 3673.14,619.23 3679.62,612.75 3808.56,612.75 3822.24,626.43 C80.1@3822.24,639.94 3822.24,659.34 v1(3806.58,675) ; v1(4100.04,-37.59) 4100.04,-36.78 4103.68,-33.15 4103.68,17.49 4103.71,224.27 4128.47,249.03 4196.34,249.03 4234.99,287.69 4234.99,354.89 4173.75,416.13 v1@4173.75,500.47
AM263_ADC_VREFHI_G2: C76.1 C78.1 S2.5 U1.V6 | length 3412.3
  Top Layer w15: U1.V6@3554.61,697.36 v1(3554.61,675) 3554.61,674.19 3547.3,666.88 3547.3,564.86 3563.17,548.98 C76.1@3563.17,548
  SIG 1 w20: v1(1785,790) 1785,762.11 1848.13,698.98 1848.13,530.65 1868.77,510 1907.02,510 1932.6,535.58 1932.6,551.74 1965.85,585 2159.9,585 2192.91,618.02 2452.89,618.02 2470.91,600 2589.93,600 2609.93,580 2829.51,580 2858.2,608.68 3060.94,608.68 3080.34,628.09 3251.52,628.09 3313.53,566.07 3313.53,519.07 3305.69,511.22 3305.69,428.44 3349.88,384.24 3409.9,384.24 3512.1,486.45 3549.69,486.45 3562.98,499.74 3562.98,648.64 3554.61,657 v1(3554.61,675)
  Bottom Layer w15: S2.5@1501.87,1040 1547.96,1040 1571.8,1063.85 1571.8,1136.8 1617.62,1182.62 1655,1182.62 1740.03,1097.59 1740.03,1024.7 1760,1004.73 1760,815 v1(1785,790) ; C78.1@3546.74,644.44 3546.83,644.44 3551.14,648.75 3551.14,670.72 3554.61,674.19 v1(3554.61,675)
AM263_ADC_VREFLO_G01: C77.2 C79.2 C80.2 R44.2 U1.V11 U1.V13 | length 376.4
  Top Layer w4: v1(3775.09,675) U1.V13@3775.09,697.36
  Top Layer w13: C77.2@3691,545.88 3691,546.86 3703.2,559.06 3716.72,559.06 3725.05,567.39 3725.05,634.28 3717.67,641.66 3717.67,643.71 3712.59,648.79 3712.59,665.87 v1@3712.59,678.71 ; C77.2@3691.24,545.64 3691.24,493.73 R44.2@3691.48,493.49 ; U1.V11@3712.09,697.36 3712.34,697.11 3712.34,681.48 3713.76,680.07 v1(3713.76,678.71)
  Bottom Layer w15: C79.2@3710.92,649.09 3710.92,675.06 3713.76,677.9 v1(3713.76,678.71) ; C79.2@3718.43,639.94 C80.2@3775,639.94 3775,674.91 v1(3775.09,675)
AM263_ADC_VREFLO_G2: C76.2 C78.2 R307.2 U1.V7 | length 346.5
  Top Layer w13: R307.2@3553.62,424.69 3553.62,434.02 3563.17,443.57 C76.2@3563.17,480.09 ; C76.2@3563.17,485.01 3563.17,485.99 3575.37,498.19 3588.27,498.19 3595.89,505.81 3595.89,575.17 3567.6,603.46 3567.6,656.07 3577.4,665.87 v1@3586.11,674.58 ; v1@3586.11,674.19 U1.V7@3586.11,697.36
  Bottom Layer w15: v1(3586.11,675) 3586.11,674.19 3589.58,670.72 3589.58,665.87 3589.58,648.75 3593.89,644.44 C78.2@3593.98,644.44
AM263_ATESTV0: U1.U3
AM263_ATESTV1: U1.V2
AM263_BP_MUX_SEL_GPIO63: R298.2 R300.2 U1.G4 U51.1 U52.9 U52.10 | length 7073.8
  Top Layer w5.3: v1(4141.03,1594.24) 4156.84,1594.24 4167.8,1583.28 U51.1@4167.8,1567.48 ; U52.9@4479.96,520 4543.01,520 v1(4555,531.99) 4547.31,539.68 U52.10@4479.96,539.68
  Top Layer w10: v1(3475.87,1059.57) U1.G4@3491.62,1043.82
  SIG 1 w4.75: v1(3365.64,1414.46) 3338.69,1441.41 3167.97,1441.41 2959.37,1232.8 2829.62,1232.8 2752.31,1155.49 2752.31,1128.83 2771.14,1110 2874.5,1110 2892.5,1092 2966.39,1092 2983.37,1075.02 3341.11,1075.02 3341.19,1074.94 3460.5,1074.94 v1(3475.87,1059.57)
  SIG 1 w5.3: v1(4555,531.99) 4573.17,550.16 5092.7,550.16 5101.57,541.29 5147.42,541.29 5173.32,515.39 5432.82,515.39 5455.21,493 5494.31,493 v1(5504.39,503.09)
  Bottom Layer w5.3: v1(3365.64,1414.46) 3388.74,1391.35 3413.03,1391.35 3477.8,1456.12 3530.51,1456.12 3576.52,1502.14 3576.52,1535.73 3563.62,1548.63 3563.62,1595.14 3575.06,1606.58 3637.63,1606.58 3657.49,1626.43 3776.69,1626.43 3791.44,1611.68 3791.44,1606.73 3841.69,1556.48 4049.68,1556.48 4087.44,1594.24 v1(4141.03,1594.24) 4151.08,1594.24 4162.89,1582.43 R298.2@4162.89,1565.49 R300.2@4162.89,1502.52 4162.89,1476.91 4173,1466.79 4255.75,1466.79 4303.96,1515 4323.5,1515 4385.8,1577.3 4508.93,1577.3 4544.26,1541.98 4568.98,1541.98 4633.54,1606.54 4925.54,1606.54 5062,1743 5614.94,1743 ; v1(5504.39,503.09) 5505,503.69 5505,738.59 5564.61,798.2 5763.18,798.2 5822.85,857.87 5822.85,1211.72 5813.39,1221.18 5813.39,1324.3 5818.5,1329.42 5818.5,1551.34 5783.8,1586.04 5783.8,1618.98 5659.78,1743 5631.18,1743 ; 5614.97,1743.04 5631.15,1743.04
AM263_CAN_STB_GPIO51: R248.2 U1.D1 | length 6115.1
  Top Layer w4: 3365.64,1138.31 U1.D1@3397.13,1138.31
  Top Layer w5.3: 3365.64,1138.31 3357.89,1138.31 3285.14,1211.06 3172.44,1211.06 3141,1242.5 3113,1242.5 3096.28,1259.22 3096.28,1297.41 3084.85,1308.85 3084.85,1328.14 3111.6,1354.89 3111.6,1660.22 3173.68,1722.3 3651.74,1722.3 3696.81,1767.37 3696.81,1964.95 3716.86,1985 3872.68,1985 v1(3885.32,1972.36)
  Bottom Layer w5.3: v1(3885.32,1972.36) 3982.97,2070 5570,2070 6011.25,1628.75 6011.25,1590.07 6029.88,1571.45 6029.88,772.38 6005,747.5 6005,533.66 6170,368.66 6247.07,368.66 6458.49,157.24 R248.2@6705,157.24
AM263_CLKOUT0: R4.2 R118.1 TP1.1 | length 5785.2
  Top Layer w5.3: TP1.1@2948.87,772.75 2948.87,778.07 v1(2972.32,801.52) 2989.85,819.06 R4.2@3071.22,819.06
  SIG 1 w4.75: v1(5417.49,1788.61) 5446.85,1759.25 5820.75,1759.25 5834.25,1745.75 5901.33,1745.75 v1(5915,1759.42)
  Bottom Layer w5.3: v1(2972.32,801.52) 2972.32,958.82 2994.52,981.02 2994.52,1341.6 3167.93,1515 3239.12,1515 3289.12,1465 3430,1465 3463.9,1498.9 3463.9,1628.89 3527.85,1692.84 3561.09,1692.84 3574.02,1679.91 3602.38,1679.91 3613.37,1668.92 3699.68,1668.92 3729.43,1698.66 3782.13,1698.66 3787.95,1692.84 3790.34,1692.84 3835,1648.18 3835,1623.13 3859.25,1598.88 3964.83,1598.88 3976.94,1610.98 3976.94,1632.53 4033.33,1688.92 4758.09,1688.92 4761.19,1692.03 4951.03,1692.03 5047.61,1788.61 v1(5417.49,1788.61) ; v1(5915,1759.42) 6021.85,1652.57 6021.85,1594.46 6040.48,1575.84 6040.48,762.98 6021.85,744.35 6021.85,545.04 6180,386.89 6267.03,386.89 6332.54,321.38 R118.1@6370,321.38
AM263_CLKOUT0_R: R4.1 U1.M2 | length 345.9
  Top Layer w4: 3389.45,870.59 3412.88,870.59 U1.M2@3428.63,886.34
  Top Layer w5.3: R4.1@3110.59,819.06 3143.06,851.54 3370.39,851.54 3389.45,870.59
AM263_DAC_OUT1: J1/J3.30 R45.1 | length 1466.4
  Top Layer w5.3: R45.1@3378.72,300.24 3378.72,250.34 v1(3468.83,160.23)
  Bottom Layer w5.3: J1/J3.30@2354.17,200 2364,209.83 2388.14,209.83 2423.79,245.48 2452.41,245.48 2463.85,256.91 2463.85,285.54 2519.46,341.15 2977.58,341.15 3001.97,316.76 3001.97,275.76 3044.43,233.3 3119.49,233.3 3119.81,233.61 3136.96,233.61 3162.14,208.43 3256.32,208.43 3260.64,204.12 3367.28,204.12 3393.78,177.62 3438.82,177.62 3441.49,174.95 3454.11,174.95 v1(3468.83,160.23)
AM263_DAC_OUT2: R3.1 U52.23 | length 1251.3
  Top Layer w5.3: v1(3425.19,267.39) R3.1@3425.19,298.84 ; v1(4062.43,447.21) 4062.43,450.65 4066.49,454.71 4066.49,484.89 4066.57,484.98 4066.57,582.1 4078.38,593.91 4214.14,593.91 4278.03,657.8 U52.23@4350.04,657.8
  Bottom Layer w5.3: v1(3425.19,267.39) 3429.5,271.69 3429.5,273.01 3441.84,285.35 3467.03,285.35 3511.35,241.04 3650.77,241.04 3657.07,234.74 3732.68,234.74 3734.9,232.51 3772.03,232.51 3807.33,267.81 3858.71,267.81 3967.68,376.78 4012.69,376.78 4062.43,426.52 v1(4062.43,447.21)
AM263_DAC_OUT2_SDFM0_CLK3: J5/J7.70 U52.14 | length 871.6
  Top Layer w5.3: U52.14@4479.96,618.43 4692.09,618.43 4789.92,520.59 v1(4950.56,520.59)
  Bottom Layer w5.3: J5/J7.70@4854.17,200 4912.92,258.75 4912.92,481.53 4950.56,519.16 v1(4950.56,520.59)
AM263_DAC_OUT_R: R3.2 R45.2 U1.T5 | length 519.4
  Top Layer w5.3: R45.2@3378.72,339.61 3423.8,339.61 3424.55,340.36 3424.55,380.01 3410.68,393.88 v1(3410.68,426) ; R3.2@3424.55,338.85 R3.2@3425.19,338.21
  Top Layer w10: v1(3507.37,744.61) U1.T5@3523.12,760.35
  SIG 1 w4.75: v1(3410.68,426) 3411.31,426.64 3411.31,502.69 3495,586.37 3495,665.87 3495,698.34 3507.37,710.71 v1(3507.37,744.61)
AM263_EPWM0_A: J2/J4.11 R46.1 | length 1247.9
  Top Layer w5.3: R46.1@3194.16,1470.17 3194.16,1606.66 3246.77,1659.27 v1(3260.06,1659.27)
  Bottom Layer w5.3: J2/J4.11@2354.17,1900 2358.69,1895.48 2358.69,1864.64 2450.87,1772.47 3146.87,1772.47 v1(3260.06,1659.27)
AM263_EPWM0_A_R: R46.2 U1.B2 | length 343.2
  Top Layer w4: 3386.77,1264.29 3387.52,1263.54 3389.53,1263.54 3397.44,1255.64 3397.58,1255.64 3412.88,1240.34 3412.88,1217.05 U1.B2@3428.63,1201.3
  Top Layer w5.3: R46.2@3194.16,1430.8 3220.27,1430.8 3386.77,1264.29
AM263_EPWM0_B: J6/J8.59 R47.1 | length 1372
  Top Layer w5.3: R47.1@3185.32,1384 3185.32,1398.68 3173,1411 3173,1616.4 3268.3,1711.7 3656.13,1711.7 3710.24,1765.8 3710.24,1911.11 3718.05,1918.92 3781.69,1918.92 3801.93,1898.69 3874.01,1898.69 3916.36,1941.04 4013.14,1941.04 J6/J8.59@4054.17,1900
AM263_EPWM0_B_R: R47.2 U1.B1 | length 264.5
  Top Layer w4: 3365.64,1232.8 U1.B1@3397.13,1201.3
  Top Layer w5.3: R47.2@3224.69,1384 3242.43,1384 3356.5,1269.93 3356.5,1241.93 3365.64,1232.8
AM263_EPWM1_A: J2/J4.37 R48.1 | length 1950.4
  Top Layer w5.3: v1(3222,1492) 3222,1594.5 v1(3233,1605.5)
  Bottom Layer w5.3: J2/J4.37@1754.17,1800 1800.03,1754.15 3058.39,1754.15 3064.78,1747.76 3129.24,1747.76 3233,1644 v1(3233,1605.5) v1@3233,1603.5 ; R48.1@3065,1345 3065,1397.08 3159.92,1492 v1(3222,1492)
AM263_EPWM1_A_R: R48.2 U1.D3 | length 475.4
  Top Layer w10: v1(3444.38,1154.06) U1.D3@3460.12,1138.31
  SIG 1 w4.75: v1(3104.37,1316.94) 3104.37,1286.87 3171.24,1220 3292.05,1220 3357.99,1154.06 v1(3444.38,1154.06)
  Bottom Layer w5.3: v1(3104.37,1316.94) R48.2@3104.37,1345
AM263_EPWM1_B: J2/J4.38 R49.1 | length 1950.5
  Top Layer w5.3: R49.1@3127.82,1265.5 3127.82,1281.37 3121.87,1287.32 3121.87,1303 3128.62,1309.75 3128.62,1575.38 3122.69,1581.31 3122.69,1643.93 3138.03,1659.27 v1(3138.27,1659.27)
  Bottom Layer w5.3: J2/J4.38@1654.17,1800 1710.63,1743.55 3033.79,1743.55 3037.34,1740 3057.54,1740 v1(3138.27,1659.27)
AM263_EPWM1_B_R: R49.2 U1.D2 | length 327
  Top Layer w4: 3365.64,1155.38 3411.56,1155.38 U1.D2@3428.63,1138.31
  Top Layer w5.3: R49.2@3167.19,1265.5 3167.19,1243.51 3186.94,1223.76 3287.43,1223.76 3355.81,1155.38 3365.64,1155.38
AM263_EPWM2_A: J2/J4.39 R50.1 | length 2054.8
  Top Layer w5.3: R50.1@3185.32,1343.5 3168.5,1343.5 3161.86,1350.14 3161.86,1632.87 v1(3188.27,1659.27)
  Bottom Layer w5.3: J2/J4.39@1554.17,1800 1621.23,1732.95 3015.72,1732.95 3022.13,1726.54 3035.81,1726.54 3122.6,1639.75 3168.74,1639.75 v1(3188.27,1659.27)
AM263_EPWM2_A_R: R50.2 U1.C2 | length 293.2
  Top Layer w4: 3379.96,1195.78 3390.19,1185.55 3412.88,1185.55 U1.C2@3428.63,1169.8
  Top Layer w5.3: R50.2@3224.69,1343.5 3246.05,1343.5 3263.55,1326 3279.32,1326 3336.25,1269.07 3336.25,1246.25 3379.96,1202.54 3379.96,1195.78
AM263_EPWM2_B: J2/J4.40 R51.1 | length 2087.8
  Top Layer w5.3: v1(3142.21,1609.27) 3142.21,1344.79 3183.5,1303.5 R51.1@3185.32,1303.5
  Bottom Layer w5.3: J2/J4.40@1454.17,1800 1531.83,1722.35 3011.33,1722.35 3124.4,1609.27 v1@3138.27,1609.27
AM263_EPWM2_B_R: R51.2 U1.C1 | length 241.8
  Top Layer w5.3: R51.2@3224.69,1303.5 3264.01,1303.5 3315.77,1251.75 3315.77,1227.91 3373.87,1169.8 U1.C1@3397.13,1169.8
AM263_EPWM3_A: J6/J8.77 R52.1 | length 2046.6
  Top Layer w5.3: R52.1@3060.5,1261.61 3045.56,1261.61 3040.98,1266.19 3040.98,1302.49 3101,1362.51 3101,1664.61 3169.29,1732.9 3567.56,1732.9 3611.17,1776.51 3611.17,1925 3696.17,2010 4206.71,2010 4298.21,1918.49 4298.21,1844.04 J6/J8.77@4254.17,1800
AM263_EPWM3_A_R: R52.2 U1.E2 | length 420.3
  Top Layer w4: 3365.64,1122.56 3412.88,1122.56 U1.E2@3428.63,1106.81
  Top Layer w5.3: R52.2@3060.5,1222.24 3080.24,1222.24 3085.5,1227.5 3126,1227.5 3154,1199.5 3275.03,1199.5 3351.97,1122.56 3365.64,1122.56
AM263_EPWM3_B: J6/J8.78 R53.1 | length 1596.1
  Bottom Layer w5.3: R53.1@2905.32,1191.34 2905.32,1267.38 3167.69,1529.75 3345.49,1529.75 3420.48,1604.74 3420.48,1633.55 3479.77,1692.84 3512.86,1692.84 3523.46,1703.44 3566.83,1703.44 3579.76,1690.51 3606.77,1690.51 3617.28,1680 3695.78,1680 3725.04,1709.26 3788.91,1709.26 3806.14,1692.03 3904.37,1692.03 3942.34,1730 4084.17,1730 J6/J8.78@4154.17,1800
AM263_EPWM3_B_R: R53.2 U1.E3 | length 564.1
  Top Layer w10: v1(3444.38,1122.56) U1.E3@3460.12,1106.81
  SIG 1 w4.75: v1(2944.69,1159.45) 2982.55,1159.45 3019.44,1122.56 v1(3444.38,1122.56)
  Bottom Layer w5.3: v1(2944.69,1159.45) R53.2@2944.69,1186.34
AM263_EPWM9_A: J6/J8.75 R9.1 | length 2468.5
  Top Layer w5.3: R9.1@2905.09,1088.11 2905.09,1109.45 2914.56,1118.92 2914.56,1270.53 3030.1,1386.07 3030.1,1717.1 3213.9,1900.9 3213.9,1923.4 3325.85,2035.35 4201.06,2035.35 4310.36,1926.06 4310.36,1777.28 4328.68,1758.96 4413.14,1758.96 J6/J8.75@4454.17,1800
AM263_EPWM9_A_R: R9.2 U1.G1 | length 471
  Top Layer w4: 3365.64,1043.82 U1.G1@3397.13,1043.82
  Top Layer w5.3: R9.2@2944.46,1088.11 2963.89,1088.11 2999.38,1052.62 3315.6,1052.62 3324.41,1043.82 3365.64,1043.82
AM263_EPWM9_B: J6/J8.76 R12.1 | length 2579.5
  Top Layer w5.3: R12.1@2905.09,985.05 2903.12,985.05 2872.15,1016.01 2872.15,1106.7 2892.4,1126.95 2892.4,1278.35 3008.9,1394.85 3008.9,1725.88 3192.7,1909.68 3192.7,1932.18 3319.91,2059.39 4303.93,2059.39 4310.46,2052.85 4313.32,2050 4403.32,1960 4403.32,1849.15 J6/J8.76@4354.17,1800
AM263_EPWM9_B_R: R12.2 U1.J2 | length 501.2
  Top Layer w4: 3365.64,995 3414.46,995 U1.J2@3428.63,980.83
  Top Layer w5.3: R12.2@2944.46,985.05 2994.95,985.05 3003.47,976.53 3331.53,976.53 3350,995 3365.64,995
AM263_EPWM11_A: J6/J8.51 R13.1 | length 2801.9
  Top Layer w5.3: R13.1@2905.09,1031.64 2903.12,1031.64 2882.75,1052.01 2882.75,1102.31 2903,1122.56 2903,1273.96 3019.5,1390.46 3019.5,1721.49 3203.3,1905.29 3203.3,1927.79 3324.3,2048.79 4246.21,2048.79 v1(4295,2000)
  Bottom Layer w5.3: v1(4295,2000) 4754.17,2000 J6/J8.51@4854.17,1900
AM263_EPWM11_A_R: R13.2 U1.H1 | length 481.5
  Top Layer w4: 3365.64,1012.32 U1.H1@3397.13,1012.32
  Top Layer w5.3: R13.2@2944.46,1031.64 2975.36,1031.64 3019.87,987.13 3327.14,987.13 3352.33,1012.32 3365.64,1012.32
AM263_EPWM11_B: J6/J8.52 R99.1 | length 2991
  Top Layer w5.3: R99.1@2903.12,929.62 2880.38,929.62 2861.55,948.45 2861.55,1111.09 2881.8,1131.34 2881.8,1282.74 2998.3,1399.24 2998.3,1730.27 3182.1,1914.07 3182.1,1936.57 3318.62,2073.09 4548.52,2073.09 4609.68,2011.93 4609.68,1872.38 4627.79,1854.27 4709.78,1854.27 4754.17,1898.66 J6/J8.52@4754.17,1900
AM263_EPWM11_B_R: R99.2 U1.J1 | length 473.9
  Top Layer w4: 3365.64,980.83 U1.J1@3397.13,980.83
  Top Layer w5.3: R99.2@2944.46,929.62 2985.36,929.62 3017.91,962.16 3341.53,962.16 3360.19,980.83 3365.64,980.83
AM263_EPWM12_A: J6/J8.53 R280.1 | length 2922.6
  Top Layer w5.3: R280.1@2905.09,881.94 2877.09,881.94 2850.95,908.08 2850.95,1115.48 2871.2,1135.73 2871.2,1287.13 2987.7,1403.63 2987.7,1734.66 3171.5,1918.46 3171.5,1940.96 3314.22,2083.69 4597.04,2083.69 4654.17,2026.55 J6/J8.53@4654.17,1900
AM263_EPWM12_A_R: R280.2 U1.K2 | length 512.1
  Top Layer w4: 3365.64,933.58 3412.88,933.58 U1.K2@3428.63,949.33
  Top Layer w5.3: R280.2@2944.46,881.94 2962.52,900 3102.62,900 3136.2,933.58 3365.64,933.58
AM263_EPWM12_B: J6/J8.57 R281.1 | length 1886.5
  Bottom Layer w5.3: R281.1@2905.32,1089.6 2882.98,1111.93 2882.98,1260.04 3163.3,1540.35 3341.1,1540.35 3409.88,1609.13 3409.88,1637.94 3475.38,1703.44 3508.47,1703.44 3519.07,1714.04 3572.39,1714.04 3585.32,1701.11 3611.16,1701.11 3620.24,1692.03 3692.82,1692.03 3720.65,1719.86 3793.3,1719.86 3810.53,1702.63 3825.62,1702.63 3863.89,1740.9 4061.79,1740.9 4104.82,1783.93 4104.82,1820 4134.82,1850 4204.17,1850 J6/J8.57@4254.17,1900
AM263_EPWM12_B_R: R281.2 U1.J4 | length 612.5
  Top Layer w10: v1(3475.87,996.57) U1.J4@3491.62,980.83
  SIG 1 w4.75: v1(2944.46,1061) 2958.26,1047.2 3129.76,1047.2 3168.53,1008.44 3303.95,1008.44 3308.15,1012.63 3459.82,1012.63 v1(3475.87,996.57)
  Bottom Layer w5.3: v1(2944.46,1061) 2944.69,1061.23 R281.2@2944.69,1089.6
AM263_EPWM13_A: J6/J8.79 R59.1 | length 1708.3
  Bottom Layer w5.3: R59.1@2905.32,1031.51 2890.47,1031.51 2872.38,1049.6 2872.38,1264.43 3158.91,1550.95 3336.71,1550.95 3399.28,1613.52 3399.28,1642.33 3470.99,1714.04 3504.08,1714.04 3514.68,1724.64 3576.78,1724.64 3589.71,1711.71 3615.55,1711.71 3624.63,1702.63 3688.43,1702.63 3716.26,1730.46 3797.69,1730.46 3814.92,1713.23 3821.23,1713.23 3859.5,1751.5 4005.67,1751.5 J6/J8.79@4054.17,1800
AM263_EPWM13_A_R: R59.2 U1.K4 | length 602
  Top Layer w10: v1(3475.87,933.58) U1.K4@3491.62,949.33
  SIG 1 w4.75: v1(2971.5,1007.83) 2994.33,985 3424.46,985 v1(3475.87,933.58)
  Bottom Layer w5.3: R59.2@2944.69,1031.51 2961.49,1031.51 2971.5,1021.5 v1(2971.5,1007.83)
AM263_EPWM13_B: J6/J8.80 R60.1 | length 1673.4
  Bottom Layer w5.3: R60.1@2906.12,985.05 2886.98,985.05 2861.78,1010.25 2861.78,1273.57 3149.76,1561.55 3332.32,1561.55 3388.68,1617.91 3388.68,1646.72 3477.2,1735.24 3581.17,1735.24 3594.1,1722.31 3619.94,1722.31 3626.93,1715.32 3686.13,1715.32 3711.87,1741.06 3802.08,1741.06 3815.88,1727.26 3820.27,1727.26 3855.11,1762.1 3916.27,1762.1 J6/J8.80@3954.17,1800
AM263_EPWM13_B_R: R60.2 U1.K3 | length 564.1
  Top Layer w10: v1(3444.38,933.58) U1.K3@3460.12,949.33
  SIG 1 w4.75: v1(2947.46,958.15) 2956.94,967.63 3410.33,967.63 v1(3444.38,933.58)
  Bottom Layer w5.3: v1(2947.46,958.15) R60.2@2947.46,985.05
AM263_EPWM14_A: J2/J4.35 R282.1 | length 4507.8
  Top Layer w5.3: J2/J4.35@1954.17,1800 1985.38,1768.8 1985.38,1413.41 2045,1353.78 v1(2045,1265.64) ; v1(3835.62,204.48) 3835.62,156.1 3822.24,142.72 3822.24,97.65 3851.53,68.36 3851.53,30.74 3860.68,21.59 3964.98,21.59 4004.71,61.32 4004.71,124.18 4027.48,146.95 4072.51,146.95 4096.41,170.85 4096.41,373.47 4049.76,420.11 4049.76,432.27 4037,445.03 4037,468.53 4043.66,475.2 4043.66,503.25 R282.1@4044.18,503.77
  Bottom Layer w5.3: v1(2045,1265.64) 1961.44,1182.08 1961.44,1071.08 2002,1030.52 2002,868.21 1949.19,815.4 1949.19,607.06 2065,491.25 2065,375.09 2123.89,316.2 2440.38,316.2 2497.13,372.95 2990.76,372.95 3034.28,329.43 3034.28,288.43 3055.69,267.02 3120.1,267.02 3160.85,307.77 3234.67,307.77 3250.44,292 3250.44,259.29 3273.81,235.92 3381.32,235.92 3404.34,212.9 3476.05,212.9 3498.55,190.41 3621.41,190.41 3679.24,132.58 3731.67,132.58 3803.58,204.48 v1(3835.62,204.48)
AM263_EPWM14_A_R: R282.2 U1.V17 | length 251.5
  Top Layer w5.3: U1.V17@3901.07,697.36 3901.07,694.53 3906.32,689.29 3906.32,665.87 3906.32,660.14 3917.68,648.77 3982.52,648.77 4027.53,603.76 4027.53,561.76 4044.18,545.11 R282.2@4044.18,543.14
AM263_EPWM14_B: J2/J4.36 R283.1 | length 4144.8
  Top Layer w5.3: J2/J4.36@1854.17,1800 1954.17,1700 1954.17,1306.47 v1(1995,1265.64)
  Bottom Layer w5.3: v1(1995,1265.64) 1950.84,1221.48 1950.84,1064.16 1991.4,1023.6 1991.4,872.6 1938.59,819.79 1938.59,602.67 2050.55,490.7 2050.55,374.55 2119.5,305.6 2444.77,305.6 2501.52,362.35 2986.37,362.35 3023.18,325.54 3023.18,284.54 3051.3,256.42 3144.13,256.42 3170.92,229.63 3265.1,229.63 3269.42,225.32 3376.93,225.32 3399.95,202.3 3400.6,202.3 3401.89,201.01 3472.14,201.01 3494.78,178.36 3616.31,178.36 3675.17,119.51 3733.83,119.51 3798.69,184.36 3843.11,184.36 3872.18,213.43 3872.18,236.3 3970.5,334.63 4057.66,334.63 4133.57,410.54 4133.57,464.05 4116.91,480.71 4083.04,480.71 4058.76,505 R283.1@4040,505
AM263_EPWM14_B_R: R283.2 U1.T16 | length 319.7
  Top Layer w10: U1.T16@3869.57,760.35 v1(3885.32,744.61)
  SIG 1 w4.75: v1(3885.32,744.61) 3931.83,744.61 4047.05,629.38 v1(4047.05,571.82)
  Bottom Layer w5.3: R283.2@4040,544.37 4040,546.48 4047.05,553.53 v1(4047.05,571.82)
AM263_EPWM15_A: J2/J4.34 R284.1 | length 4299.4
  Top Layer w5.3: J2/J4.34@2054.17,1800 2054.17,1669.87 2025,1640.7 2025,1443.86 2070.89,1397.97 2070.89,1289.75 v1(2095,1265.64)
  Bottom Layer w5.3: v1(2095,1265.64) 2067.11,1293.54 1981.42,1293.54 1931.83,1243.95 1931.83,1063.17 1980.8,1014.2 1980.8,876.99 1927.99,824.18 1927.99,598.28 2006.93,519.33 2006.93,355.45 2067.39,295 2449.16,295 2505.91,351.75 2981.98,351.75 3012.57,321.15 3012.57,280.15 3048.51,244.21 3141.35,244.21 3166.53,219.03 3260.71,219.03 3265.03,214.72 3372.1,214.72 3397.23,189.58 3467.54,189.58 3491.02,166.11 3561.9,166.11 3562.27,166.48 3579.87,166.48 3589.89,156.46 3589.89,145.73 3609.3,126.33 3638.2,126.33 3657.61,106.92 3737.37,106.92 3804.21,173.76 3847.5,173.76 3882.78,209.04 3882.78,231.91 3972.65,321.78 4063.85,321.78 4146.91,404.85 4146.91,483.39 4135.13,495.18 4135.13,497.81 R284.1@4127.93,505
AM263_EPWM15_A_R: R284.2 U1.P15 | length 582.5
  Top Layer w10: U1.P15@3838.08,823.35 v1(3853.83,807.6)
  SIG 1 w4.75: v1(3853.83,807.6) 3869.2,822.97 3914.73,822.97 3914.84,822.86 4105.88,822.86 4145,783.74 4145,584.48 v1(4132.93,572.41)
  Bottom Layer w5.3: R284.2@4127.93,544.37 4127.93,563.98 4132.93,568.98 v1(4132.93,572.41)
AM263_EPWM15_B: J5/J7.45 R285.1 | length 622.2
  Top Layer w5.3: R285.1@4086.47,505 4081.95,500.48 4081.95,402.91 4107.01,377.86 4107.01,172 4132.05,146.95 4307.22,146.95 J5/J7.45@4354.17,100
AM263_EPWM15_B_R: R285.2 U1.R16 | length 404.4
  Top Layer w5.3: R285.2@4086.47,546.32 v1(4086.47,574.38)
  Top Layer w10: U1.R16@3869.57,791.85 v1(3885.32,776.1)
  SIG 1 w4.75: v1(3885.32,776.1) 3887.75,773.67 4001.15,773.67 4089.59,685.24 4089.59,583.79 4089,583.2 4089,576.92 v1(4086.47,574.38)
